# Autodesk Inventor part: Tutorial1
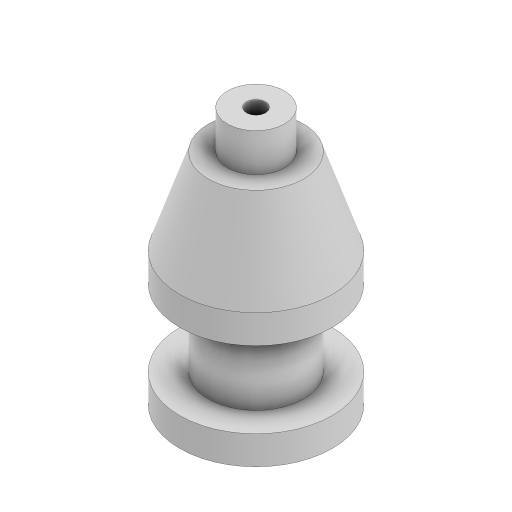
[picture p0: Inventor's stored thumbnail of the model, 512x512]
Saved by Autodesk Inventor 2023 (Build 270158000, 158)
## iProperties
Created: 2022-07
Part Number: Tutorial1
Material: Generic
Document SubType Name: Modeling
Designer: LENOVO-CADCIM
Density: 1 g/cm^3
Appearance: Default
Author: LENOVO-CADCIM
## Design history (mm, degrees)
sketch "Sketch1"
  geometry: L1 (10, 0)-(10, 270); L2 (10, 270)-(30, 270); L3 (30, 270)-(30, 230); L4 (30, 230)-(50, 230); L5 (50, 230)-(80, 140); L6 (80, 140)-(80, 110); L7 (80, 110)-(50, 110); L8 (50, 110)-(50, 30); L9 (50, 30)-(80, 30); L10 (80, 30)-(80, 0); L11 (80, 0)-(10, 0); L12 (0, 0)-(0, 270)
  constraints: 24 end point, 8 perpendicular, 2 vertical, 1 collinear, 1 parallel, 1 point on line
  dimensions: "d0" = 30 distance between parallel lines of L11 L9; "d1" = 80 distance between parallel lines of L7 L9; "d2" = 30 distance of L5.end L6.end; "d3" = 230 distance between parallel lines of L4 L11; "d4" = 40 distance between parallel lines of L4 L2; "d6" = 160 diameter of L10.end L12; "d7" = 100 diameter of L8 L12; "d8" = 20 diameter of L1 L12; "d9" = 60 diameter of L3 L12; "d10" = 100 diameter of L4.end L12
revolve "Revolution1" sketch "Sketch1" stored, may be unused: angle "d11" = 90 deg
body "Solid1"
